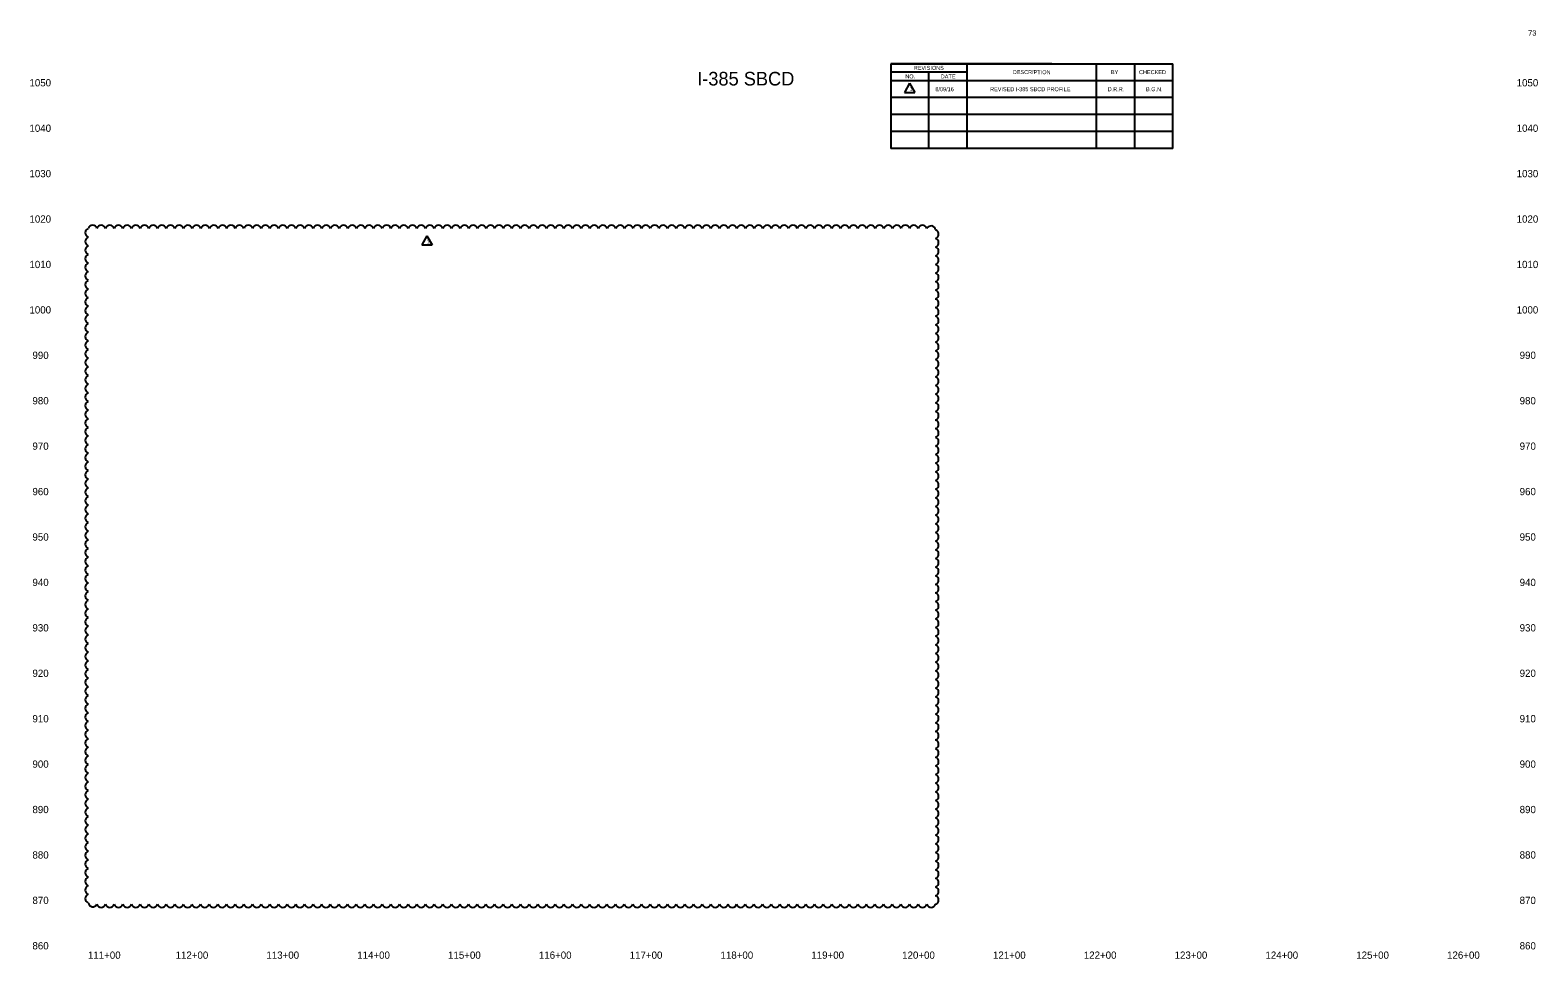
# Model space of a CAD drawing. Extents: x 16974303 to 16975963, y 12564077 to 12565100.
import ezdxf

# ---------------------------------------------------------------- set-up
doc = ezdxf.new("R2010")
doc.units = 0
for name, color, linetype in [('RD_DDB_ElevTX', 7, 'Continuous'), ('RD_DDB_StaTX', 7, 'Continuous'), ('RD_SHT_TX', 7, 'Continuous')]:
    doc.layers.add(name, color=color, linetype=linetype)

msp = doc.modelspace()

# ---------------------------------------------------------------- linework, layer by layer
at = {"layer": 'RD_SHT_TX'}
for p, q in [((16975251, 12565062.8), (16975561.6, 12565062.8)), ((16975428.2, 12565062.8), (16975251, 12565062.8)), ((16975251, 12565062.8), (16975251, 12564969.3)), ((16975335, 12564969.3), (16975335, 12565062.8)), ((16975477.6, 12564969.3), (16975477.6, 12565062.8)), ((16975519.6, 12564969.3), (16975519.6, 12565062.8)), ((16975561.6, 12564969.3), (16975561.6, 12565062.8)), ((16975335, 12565053.5), (16975251, 12565053.5)), ((16975561.6, 12565044.1), (16975251, 12565044.1)), ((16975271.6, 12565041.2), (16975266, 12565031)), ((16975271.6, 12565041.2), (16975277.3, 12565031)), ((16975293, 12564969.3), (16975293, 12565053.5)), ((16975561.6, 12565025.4), (16975251, 12565025.4)), ((16975266, 12565031), (16975277.3, 12565031)), ((16975561.6, 12565006.7), (16975251, 12565006.7)), ((16975561.6, 12564988), (16975251, 12564988)), ((16975561.6, 12564969.3), (16975251, 12564969.3)), ((16974740.2, 12564873.4), (16974734.5, 12564863.3)), ((16974740.2, 12564873.4), (16974745.9, 12564863.3)), ((16974734.5, 12564863.3), (16974745.9, 12564863.3))]:
    msp.add_line(p, q, dxfattribs=at)
for centre, start, end in [((16974368.9, 12564876.7), 107.5, 252.5), ((16974372.2, 12564879.9), 17.5, 162.5), ((16974381.7, 12564879.9), 17.5, 162.5), ((16974391.2, 12564879.9), 17.5, 162.5), ((16974400.8, 12564879.9), 17.5, 162.5), ((16974410.3, 12564879.9), 17.5, 162.5), ((16974419.8, 12564879.9), 17.5, 162.5), ((16974429.3, 12564879.9), 17.5, 162.5), ((16974438.8, 12564879.9), 17.5, 162.5), ((16974448.4, 12564879.9), 17.5, 162.5), ((16974457.9, 12564879.9), 17.5, 162.5), ((16974467.4, 12564879.9), 17.5, 162.5), ((16974476.9, 12564879.9), 17.5, 162.5), ((16974486.4, 12564879.9), 17.5, 162.5), ((16974496, 12564879.9), 17.5, 162.5), ((16974505.5, 12564879.9), 17.5, 162.5), ((16974515, 12564879.9), 17.5, 162.5), ((16974524.5, 12564879.9), 17.5, 162.5), ((16974534, 12564879.9), 17.5, 162.5), ((16974543.6, 12564879.9), 17.5, 162.5), ((16974553.1, 12564879.9), 17.5, 162.5), ((16974562.6, 12564879.9), 17.5, 162.5), ((16974572.1, 12564879.9), 17.5, 162.5), ((16974581.6, 12564879.9), 17.5, 162.5), ((16974591.1, 12564879.9), 17.5, 162.5), ((16974600.7, 12564879.9), 17.5, 162.5), ((16974610.2, 12564879.9), 17.5, 162.5), ((16974619.7, 12564879.9), 17.5, 162.5), ((16974629.2, 12564879.9), 17.5, 162.5), ((16974638.7, 12564879.9), 17.5, 162.5), ((16974648.3, 12564879.9), 17.5, 162.5), ((16974657.8, 12564879.9), 17.5, 162.5), ((16974667.3, 12564879.9), 17.5, 162.5), ((16974676.8, 12564879.9), 17.5, 162.5), ((16974686.3, 12564879.9), 17.5, 162.5), ((16974695.9, 12564879.9), 17.5, 162.5), ((16974705.4, 12564879.9), 17.5, 162.5), ((16974714.9, 12564879.9), 17.5, 162.5), ((16974724.4, 12564879.9), 17.5, 162.5), ((16974733.9, 12564879.9), 17.5, 162.5), ((16974743.5, 12564879.9), 17.5, 162.5), ((16974753, 12564879.9), 17.5, 162.5), ((16974762.5, 12564879.9), 17.5, 162.5), ((16974772, 12564879.9), 17.5, 162.5), ((16974781.5, 12564879.9), 17.5, 162.5), ((16974791.1, 12564879.9), 17.5, 162.5), ((16974800.6, 12564879.9), 17.5, 162.5), ((16974810.1, 12564879.9), 17.5, 162.5), ((16974819.6, 12564879.9), 17.5, 162.5), ((16974829.1, 12564879.9), 17.5, 162.5), ((16974838.6, 12564879.9), 17.5, 162.5), ((16974848.2, 12564879.9), 17.5, 162.5), ((16974857.7, 12564879.9), 17.5, 162.5), ((16974867.2, 12564879.9), 17.5, 162.5), ((16974876.7, 12564879.9), 17.5, 162.5), ((16974886.2, 12564879.9), 17.5, 162.5), ((16974895.8, 12564879.9), 17.5, 162.5), ((16974905.3, 12564879.9), 17.5, 162.5), ((16974914.8, 12564879.9), 17.5, 162.5), ((16974924.3, 12564879.9), 17.5, 162.5), ((16974933.8, 12564879.9), 17.5, 162.5), ((16974943.4, 12564879.9), 17.5, 162.5), ((16974952.9, 12564879.9), 17.5, 162.5), ((16974962.4, 12564879.9), 17.5, 162.5), ((16974971.9, 12564879.9), 17.5, 162.5), ((16974981.4, 12564879.9), 17.5, 162.5), ((16974991, 12564879.9), 17.5, 162.5), ((16975000.5, 12564879.9), 17.5, 162.5), ((16975010, 12564879.9), 17.5, 162.5), ((16975019.5, 12564879.9), 17.5, 162.5), ((16975029, 12564879.9), 17.5, 162.5), ((16975038.5, 12564879.9), 17.5, 162.5), ((16975048.1, 12564879.9), 17.5, 162.5), ((16975057.6, 12564879.9), 17.5, 162.5), ((16975067.1, 12564879.9), 17.5, 162.5), ((16975076.6, 12564879.9), 17.5, 162.5), ((16975086.1, 12564879.9), 17.5, 162.5), ((16975095.7, 12564879.9), 17.5, 162.5), ((16975105.2, 12564879.9), 17.5, 162.5), ((16975114.7, 12564879.9), 17.5, 162.5), ((16975124.2, 12564879.9), 17.5, 162.5), ((16975133.7, 12564879.9), 17.5, 162.5), ((16975143.3, 12564879.9), 17.5, 162.5), ((16975152.8, 12564879.9), 17.5, 162.5), ((16975162.3, 12564879.9), 17.5, 162.5), ((16975171.8, 12564879.9), 17.5, 162.5), ((16975181.3, 12564879.9), 17.5, 162.5), ((16975190.9, 12564879.9), 17.5, 162.5), ((16975200.4, 12564879.9), 17.5, 162.5), ((16975209.9, 12564879.9), 17.5, 162.5), ((16975219.4, 12564879.9), 17.5, 162.5), ((16975228.9, 12564879.9), 17.5, 162.5), ((16975238.5, 12564879.9), 17.5, 162.5), ((16975248, 12564879.9), 17.5, 162.5), ((16975257.5, 12564879.9), 17.5, 162.5), ((16975267, 12564879.9), 17.5, 162.5), ((16975276.5, 12564879.9), 17.5, 162.5), ((16975286, 12564879.9), 17.5, 162.5), ((16975295.3, 12564879.2), 8.6221, 153.6221), ((16975298.7, 12564875.2), 287.5, 72.5), ((16974368.9, 12564867.1), 107.5, 252.5), ((16974368.9, 12564857.6), 107.5, 252.5), ((16975298.7, 12564865.7), 287.5, 72.5), ((16975298.7, 12564856.2), 287.5, 72.5), ((16974368.9, 12564848.1), 107.5, 252.5), ((16974368.9, 12564838.6), 107.5, 252.5), ((16975298.7, 12564846.6), 287.5, 72.5), ((16975298.7, 12564837.1), 287.5, 72.5), ((16974368.9, 12564829.1), 107.5, 252.5), ((16974368.9, 12564819.5), 107.5, 252.5), ((16975298.7, 12564827.6), 287.5, 72.5), ((16975298.7, 12564818.1), 287.5, 72.5), ((16974368.9, 12564810), 107.5, 252.5), ((16975298.7, 12564808.6), 287.5, 72.5), ((16974368.9, 12564800.5), 107.5, 252.5), ((16974368.9, 12564791), 107.5, 252.5), ((16975298.7, 12564799), 287.5, 72.5), ((16975298.7, 12564789.5), 287.5, 72.5), ((16974368.9, 12564781.5), 107.5, 252.5), ((16974368.9, 12564771.9), 107.5, 252.5), ((16975298.7, 12564780), 287.5, 72.5), ((16975298.7, 12564770.5), 287.5, 72.5), ((16974368.9, 12564762.4), 107.5, 252.5), ((16974368.9, 12564752.9), 107.5, 252.5), ((16975298.7, 12564761), 287.5, 72.5), ((16975298.7, 12564751.4), 287.5, 72.5), ((16974368.9, 12564743.4), 107.5, 252.5), ((16975298.7, 12564741.9), 287.5, 72.5), ((16974368.9, 12564733.9), 107.5, 252.5), ((16974368.9, 12564724.4), 107.5, 252.5), ((16975298.7, 12564732.4), 287.5, 72.5), ((16975298.7, 12564722.9), 287.5, 72.5), ((16974368.9, 12564714.8), 107.5, 252.5), ((16974368.9, 12564705.3), 107.5, 252.5), ((16975298.7, 12564713.4), 287.5, 72.5), ((16975298.7, 12564703.8), 287.5, 72.5), ((16974368.9, 12564695.8), 107.5, 252.5), ((16974368.9, 12564686.3), 107.5, 252.5), ((16975298.7, 12564694.3), 287.5, 72.5), ((16975298.7, 12564684.8), 287.5, 72.5), ((16974368.9, 12564676.8), 107.5, 252.5), ((16975298.7, 12564675.3), 287.5, 72.5), ((16974368.9, 12564667.2), 107.5, 252.5), ((16974368.9, 12564657.7), 107.5, 252.5), ((16975298.7, 12564665.8), 287.5, 72.5), ((16975298.7, 12564656.3), 287.5, 72.5), ((16974368.9, 12564648.2), 107.5, 252.5), ((16974368.9, 12564638.7), 107.5, 252.5), ((16975298.7, 12564646.7), 287.5, 72.5), ((16975298.7, 12564637.2), 287.5, 72.5), ((16974368.9, 12564629.2), 107.5, 252.5), ((16974368.9, 12564619.6), 107.5, 252.5), ((16975298.7, 12564627.7), 287.5, 72.5), ((16974368.9, 12564610.1), 107.5, 252.5), ((16975298.7, 12564618.2), 287.5, 72.5), ((16975298.7, 12564608.7), 287.5, 72.5), ((16974368.9, 12564600.6), 107.5, 252.5), ((16974368.9, 12564591.1), 107.5, 252.5), ((16975298.7, 12564599.1), 287.5, 72.5), ((16975298.7, 12564589.6), 287.5, 72.5), ((16974368.9, 12564581.6), 107.5, 252.5), ((16974368.9, 12564572), 107.5, 252.5), ((16975298.7, 12564580.1), 287.5, 72.5), ((16975298.7, 12564570.6), 287.5, 72.5), ((16974368.9, 12564562.5), 107.5, 252.5), ((16974368.9, 12564553), 107.5, 252.5), ((16975298.7, 12564561.1), 287.5, 72.5), ((16974368.9, 12564543.5), 107.5, 252.5), ((16975298.7, 12564551.5), 287.5, 72.5), ((16975298.7, 12564542), 287.5, 72.5), ((16974368.9, 12564534), 107.5, 252.5), ((16974368.9, 12564524.5), 107.5, 252.5), ((16975298.7, 12564532.5), 287.5, 72.5), ((16975298.7, 12564523), 287.5, 72.5), ((16974368.9, 12564514.9), 107.5, 252.5), ((16974368.9, 12564505.4), 107.5, 252.5), ((16975298.7, 12564513.5), 287.5, 72.5), ((16975298.7, 12564503.9), 287.5, 72.5), ((16974368.9, 12564495.9), 107.5, 252.5), ((16974368.9, 12564486.4), 107.5, 252.5), ((16975298.7, 12564494.4), 287.5, 72.5), ((16974368.9, 12564476.9), 107.5, 252.5), ((16975298.7, 12564484.9), 287.5, 72.5), ((16975298.7, 12564475.4), 287.5, 72.5), ((16974368.9, 12564467.3), 107.5, 252.5), ((16974368.9, 12564457.8), 107.5, 252.5), ((16975298.7, 12564465.9), 287.5, 72.5), ((16975298.7, 12564456.3), 287.5, 72.5), ((16974368.9, 12564448.3), 107.5, 252.5), ((16974368.9, 12564438.8), 107.5, 252.5), ((16975298.7, 12564446.8), 287.5, 72.5), ((16975298.7, 12564437.3), 287.5, 72.5), ((16974368.9, 12564429.3), 107.5, 252.5), ((16974368.9, 12564419.7), 107.5, 252.5), ((16975298.7, 12564427.8), 287.5, 72.5), ((16974368.9, 12564410.2), 107.5, 252.5), ((16975298.7, 12564418.3), 287.5, 72.5), ((16975298.7, 12564408.8), 287.5, 72.5), ((16974368.9, 12564400.7), 107.5, 252.5), ((16974368.9, 12564391.2), 107.5, 252.5), ((16975298.7, 12564399.2), 287.5, 72.5), ((16975298.7, 12564389.7), 287.5, 72.5), ((16974368.9, 12564381.7), 107.5, 252.5), ((16974368.9, 12564372.1), 107.5, 252.5), ((16975298.7, 12564380.2), 287.5, 72.5), ((16975298.7, 12564370.7), 287.5, 72.5), ((16974368.9, 12564362.6), 107.5, 252.5), ((16974368.9, 12564353.1), 107.5, 252.5), ((16975298.7, 12564361.2), 287.5, 72.5), ((16974368.9, 12564343.6), 107.5, 252.5), ((16975298.7, 12564351.6), 287.5, 72.5), ((16975298.7, 12564342.1), 287.5, 72.5), ((16974368.9, 12564334.1), 107.5, 252.5), ((16974368.9, 12564324.5), 107.5, 252.5), ((16975298.7, 12564332.6), 287.5, 72.5), ((16975298.7, 12564323.1), 287.5, 72.5), ((16974368.9, 12564315), 107.5, 252.5), ((16974368.9, 12564305.5), 107.5, 252.5), ((16975298.7, 12564313.6), 287.5, 72.5), ((16975298.7, 12564304), 287.5, 72.5), ((16974368.9, 12564296), 107.5, 252.5), ((16974368.9, 12564286.5), 107.5, 252.5), ((16975298.7, 12564294.5), 287.5, 72.5), ((16974368.9, 12564277), 107.5, 252.5), ((16975298.7, 12564285), 287.5, 72.5), ((16975298.7, 12564275.5), 287.5, 72.5), ((16974368.9, 12564267.4), 107.5, 252.5), ((16974368.9, 12564257.9), 107.5, 252.5), ((16975298.7, 12564266), 287.5, 72.5), ((16975298.7, 12564256.4), 287.5, 72.5), ((16974368.9, 12564248.4), 107.5, 252.5), ((16974368.9, 12564238.9), 107.5, 252.5), ((16975298.7, 12564246.9), 287.5, 72.5), ((16975298.7, 12564237.4), 287.5, 72.5), ((16974368.9, 12564229.4), 107.5, 252.5), ((16974368.9, 12564219.8), 107.5, 252.5), ((16975298.7, 12564227.9), 287.5, 72.5), ((16974368.9, 12564210.3), 107.5, 252.5), ((16975298.7, 12564218.4), 287.5, 72.5), ((16975298.7, 12564208.9), 287.5, 72.5), ((16974368.9, 12564200.8), 107.5, 252.5), ((16974368.9, 12564191.3), 107.5, 252.5), ((16975298.7, 12564199.3), 287.5, 72.5), ((16975298.7, 12564189.8), 287.5, 72.5), ((16974368.9, 12564181.8), 107.5, 252.5), ((16974368.9, 12564172.2), 107.5, 252.5), ((16975298.7, 12564180.3), 287.5, 72.5), ((16975298.7, 12564170.8), 287.5, 72.5), ((16974368.9, 12564162.7), 107.5, 252.5), ((16975298.7, 12564161.3), 287.5, 72.5), ((16974368.9, 12564153.2), 107.5, 252.5), ((16974368.9, 12564143.7), 107.5, 252.5), ((16975298.7, 12564151.7), 287.5, 72.5), ((16975298.7, 12564142.2), 287.5, 72.5), ((16974372.4, 12564139.7), 188.6221, 333.6221), ((16974381.6, 12564139), 197.5, 342.5), ((16974391.1, 12564139), 197.5, 342.5), ((16974400.6, 12564139), 197.5, 342.5), ((16974410.2, 12564139), 197.5, 342.5), ((16974419.7, 12564139), 197.5, 342.5), ((16974429.2, 12564139), 197.5, 342.5), ((16974438.7, 12564139), 197.5, 342.5), ((16974448.2, 12564139), 197.5, 342.5), ((16974457.8, 12564139), 197.5, 342.5), ((16974467.3, 12564139), 197.5, 342.5), ((16974476.8, 12564139), 197.5, 342.5), ((16974486.3, 12564139), 197.5, 342.5), ((16974495.8, 12564139), 197.5, 342.5), ((16974505.4, 12564139), 197.5, 342.5), ((16974514.9, 12564139), 197.5, 342.5), ((16974524.4, 12564139), 197.5, 342.5), ((16974533.9, 12564139), 197.5, 342.5), ((16974543.4, 12564139), 197.5, 342.5), ((16974553, 12564139), 197.5, 342.5), ((16974562.5, 12564139), 197.5, 342.5), ((16974572, 12564139), 197.5, 342.5), ((16974581.5, 12564139), 197.5, 342.5), ((16974591, 12564139), 197.5, 342.5), ((16974600.5, 12564139), 197.5, 342.5), ((16974610.1, 12564139), 197.5, 342.5), ((16974619.6, 12564139), 197.5, 342.5), ((16974629.1, 12564139), 197.5, 342.5), ((16974638.6, 12564139), 197.5, 342.5), ((16974648.1, 12564139), 197.5, 342.5), ((16974657.7, 12564139), 197.5, 342.5), ((16974667.2, 12564139), 197.5, 342.5), ((16974676.7, 12564139), 197.5, 342.5), ((16974686.2, 12564139), 197.5, 342.5), ((16974695.7, 12564139), 197.5, 342.5), ((16974705.3, 12564139), 197.5, 342.5), ((16974714.8, 12564139), 197.5, 342.5), ((16974724.3, 12564139), 197.5, 342.5), ((16974733.8, 12564139), 197.5, 342.5), ((16974743.3, 12564139), 197.5, 342.5), ((16974752.9, 12564139), 197.5, 342.5), ((16974762.4, 12564139), 197.5, 342.5), ((16974771.9, 12564139), 197.5, 342.5), ((16974781.4, 12564139), 197.5, 342.5), ((16974790.9, 12564139), 197.5, 342.5), ((16974800.4, 12564139), 197.5, 342.5), ((16974810, 12564139), 197.5, 342.5), ((16974819.5, 12564139), 197.5, 342.5), ((16974829, 12564139), 197.5, 342.5), ((16974838.5, 12564139), 197.5, 342.5), ((16974848, 12564139), 197.5, 342.5), ((16974857.6, 12564139), 197.5, 342.5), ((16974867.1, 12564139), 197.5, 342.5), ((16974876.6, 12564139), 197.5, 342.5), ((16974886.1, 12564139), 197.5, 342.5), ((16974895.6, 12564139), 197.5, 342.5), ((16974905.2, 12564139), 197.5, 342.5), ((16974914.7, 12564139), 197.5, 342.5), ((16974924.2, 12564139), 197.5, 342.5), ((16974933.7, 12564139), 197.5, 342.5), ((16974943.2, 12564139), 197.5, 342.5), ((16974952.8, 12564139), 197.5, 342.5), ((16974962.3, 12564139), 197.5, 342.5), ((16974971.8, 12564139), 197.5, 342.5), ((16974981.3, 12564139), 197.5, 342.5), ((16974990.8, 12564139), 197.5, 342.5), ((16975000.4, 12564139), 197.5, 342.5), ((16975009.9, 12564139), 197.5, 342.5), ((16975019.4, 12564139), 197.5, 342.5), ((16975028.9, 12564139), 197.5, 342.5), ((16975038.4, 12564139), 197.5, 342.5), ((16975047.9, 12564139), 197.5, 342.5), ((16975057.5, 12564139), 197.5, 342.5), ((16975067, 12564139), 197.5, 342.5), ((16975076.5, 12564139), 197.5, 342.5), ((16975086, 12564139), 197.5, 342.5), ((16975095.5, 12564139), 197.5, 342.5), ((16975105.1, 12564139), 197.5, 342.5), ((16975114.6, 12564139), 197.5, 342.5), ((16975124.1, 12564139), 197.5, 342.5), ((16975133.6, 12564139), 197.5, 342.5), ((16975143.1, 12564139), 197.5, 342.5), ((16975152.7, 12564139), 197.5, 342.5), ((16975162.2, 12564139), 197.5, 342.5), ((16975171.7, 12564139), 197.5, 342.5), ((16975181.2, 12564139), 197.5, 342.5), ((16975190.7, 12564139), 197.5, 342.5), ((16975200.3, 12564139), 197.5, 342.5), ((16975209.8, 12564139), 197.5, 342.5), ((16975219.3, 12564139), 197.5, 342.5), ((16975228.8, 12564139), 197.5, 342.5), ((16975238.3, 12564139), 197.5, 342.5), ((16975247.8, 12564139), 197.5, 342.5), ((16975257.4, 12564139), 197.5, 342.5), ((16975266.9, 12564139), 197.5, 342.5), ((16975276.4, 12564139), 197.5, 342.5), ((16975285.9, 12564139), 197.5, 342.5), ((16975295.4, 12564139), 197.5, 342.5)]:
    msp.add_arc(centre, 4.99, start, end, dxfattribs=at)

# ---------------------------------------------------------------- texts
at = {"layer": 'RD_DDB_ElevTX'}
for s, p in [('1050', (16974302.6, 12565037.8)), ('1050', (16975940.1, 12565037.8)), ('1040', (16974302.6, 12564987.8)), ('1040', (16975940.1, 12564987.8)), ('1030', (16974302.6, 12564937.8)), ('1030', (16975940.1, 12564937.8)), ('1020', (16974302.6, 12564887.8)), ('1020', (16975940.1, 12564887.8)), ('1010', (16974302.6, 12564837.8)), ('1010', (16975940.1, 12564837.8)), ('1000', (16974302.6, 12564787.8)), ('1000', (16975940.1, 12564787.8)), ('990', (16974305.9, 12564737.8)), ('990', (16975943.4, 12564737.8)), ('980', (16974305.9, 12564687.8)), ('980', (16975943.4, 12564687.8)), ('970', (16974305.9, 12564637.8)), ('970', (16975943.4, 12564637.8)), ('960', (16974305.9, 12564587.8)), ('960', (16975943.4, 12564587.8)), ('950', (16974305.9, 12564537.8)), ('950', (16975943.4, 12564537.8)), ('940', (16974305.9, 12564487.8)), ('940', (16975943.4, 12564487.8)), ('930', (16974305.9, 12564437.8)), ('930', (16975943.4, 12564437.8)), ('920', (16974305.9, 12564387.8)), ('920', (16975943.4, 12564387.8)), ('910', (16974305.9, 12564337.8)), ('910', (16975943.4, 12564337.8)), ('900', (16974305.9, 12564287.8)), ('900', (16975943.4, 12564287.8)), ('890', (16974305.9, 12564237.8)), ('890', (16975943.4, 12564237.8)), ('880', (16974305.9, 12564187.8)), ('880', (16975943.4, 12564187.8)), ('870', (16974305.9, 12564137.8)), ('870', (16975943.4, 12564137.8)), ('860', (16974305.9, 12564087.8)), ('860', (16975943.4, 12564087.8))]:
    msp.add_text(s, height=8, dxfattribs=at).set_placement(p)
at = {"layer": 'RD_DDB_StaTX'}
for s, p in [('111+00', (16974367, 12564077.5)), ('112+00', (16974463.5, 12564077.5)), ('113+00', (16974563.5, 12564077.5)), ('114+00', (16974663.5, 12564077.5)), ('115+00', (16974763.5, 12564077.5)), ('116+00', (16974863.5, 12564077.5)), ('117+00', (16974963.5, 12564077.5)), ('118+00', (16975063.5, 12564077.5)), ('119+00', (16975163.5, 12564077.5)), ('120+00', (16975263.5, 12564077.5)), ('121+00', (16975363.5, 12564077.5)), ('122+00', (16975463.5, 12564077.5)), ('123+00', (16975563.5, 12564077.5)), ('124+00', (16975663.5, 12564077.5)), ('125+00', (16975763.5, 12564077.5)), ('126+00', (16975863.5, 12564077.5))]:
    msp.add_text(s, height=8, dxfattribs=at).set_placement(p)
at = {"layer": 'RD_SHT_TX'}
for s, height, p in [('73', 6, (16975952.7, 12565093.6)), ('REVISIONS', 4.4, (16975276.3, 12565056)), ('CHECKED', 4.4, (16975524.3, 12565051.3)), ('I-385 SBCD', 15, (16975037.8, 12565038.8)), ('NO.', 4.4, (16975267, 12565046.6)), ('1', 4.4, (16975271.6, 12565032.7)), ('8/09/16', 4.4, (16975300.1, 12565032.5)), ('REVISED I-385 SBCD PROFILE ', 4.4, (16975360.3, 12565032.5)), ('D.R.R.', 4.4, (16975489.8, 12565032.5)), ('B.G.N.', 4.4, (16975532, 12565032.5)), ('1', 4.4, (16974740.2, 12564864.9))]:
    msp.add_text(s, height=height, dxfattribs=at).set_placement(p)
for s, height, p in [('DESCRIPTION', 4.408, (16975385.3, 12565051.4)), ('BY', 4.41, (16975493.3, 12565051.3)), ('DATE', 4.41, (16975306, 12565046.6))]:
    msp.add_text(s, height=height, rotation=359.7246, dxfattribs=at).set_placement(p)

doc.saveas('drawing.dxf')
